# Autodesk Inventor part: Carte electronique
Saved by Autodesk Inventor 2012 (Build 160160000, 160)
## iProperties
Created: 2013-08
Part Number: Carte electronique
Material: Default
Document SubType Name: Modeling
Designer: hilarion
Density: 1 g/cm^3
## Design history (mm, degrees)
node "Carte electronique1"
node "Carte electronique"
node "Base1"
